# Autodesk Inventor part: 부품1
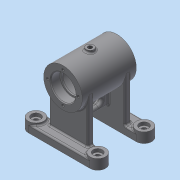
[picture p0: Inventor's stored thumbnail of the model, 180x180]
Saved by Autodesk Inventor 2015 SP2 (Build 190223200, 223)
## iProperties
Created: 2015-11
Part Number: 부품1
Material: 일반
Document SubType Name: Modeling
Designer: AMC
Density: 1 g/cm^3
Appearance: 기본값
Author: AMC
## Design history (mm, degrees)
sketch "스케치1"
  geometry: C1 r 25 at (0, 0); 1 further point
  constraints: 1 centre point, 1 coincident
  dimensions: "d0" = 50 diameter of C1
extrude "돌출1" new body sketch "스케치1" distance "d1" = 70; taper "d2" = 0 deg
sketch "스케치2"
  geometry: C1 r 5 at (0, 35); 1 further point
  constraints: 1 centre point
  dimensions: "d3" = 35 distance of point (0, 0) C1.centre; "d4" = 10 diameter of C1
extrude "돌출2" join sketch "스케치2" distance "d5" = 28; taper "d6" = 0 deg
sketch "스케치3"
  geometry: L1 (25, 70)-(-25, 70) reference; L2 (-25, 0)-(25, 0) reference; L3 (16, 70)-(16, 58); L4 (16, 58)-(14, 58); L5 (14, 58)-(14, 56); L6 (14, 56)-(21, 56); L7 (21, 56)-(21, 14); L8 (21, 14)-(14, 14); L9 (14, 14)-(14, 12); L10 (14, 12)-(16, 12); L11 (16, 12)-(16, 0); L12 (0, 70)-(0, 0)
  constraints: 20 end point, 8 perpendicular, 4 point on line, 1 midpoint, 1 vertical
  dimensions: "d7" = 32 diameter of L3 L12; "d8" = 28 diameter of L5 L12; "d9" = 42 diameter of L7 L12; "d10" = 32 diameter of L11 L12; "d11" = 42 distance of L6.end L7.end; "d12" = 12 distance of L3.start L3.end; "d13" = 12 distance of L10.end L11.end; "d120" = 2 distance of L8.end L9.end
revolve "회전1" sketch "스케치3" stored, may be unused: angle "d14" = 90 deg
sketch "스케치4"
  geometry: 2 further points
hole "구멍1" sketch "스케치4" at (0, 0) diameter "d15" = 5.188; stored, may be unused: countersink angle "d19" = 90 deg, drill point angle "d21" = 118 deg; dims "d16" = 25, "d17" = 4, "d18" = 2, "d20" = 29
node "작업 평면3"
sketch "스케치5"
  geometry: L1 (40, 75)-(-40, 75); L2 (-40, -5)-(40, -5); L3 (40, 55)-(4, 55); L4 (4, 55)-(4, 15); L5 (4, 15)-(40, 15); L6 (-4, 55)-(-40, 55); L7 (-40, 15)-(-4, 15); L8 (-4, 15)-(-4, 55); L9 (40, -5)-(40, 15); L10 (40, 55)-(40, 75); L11 (-40, 75)-(-40, 55); L12 (-40, 15)-(-40, -5); L13 (25, 70)-(-25, 70) reference; L14 (25, 0)-(25, 70) reference; L15 (-25, 0)-(25, 0) reference; L16 (-25, 0)-(-25, 70) reference; L17 (0, 70)-(0, 0); L18 (25, 35)-(-25, 35)
  constraints: 28 end point, 7 parallel, 4 midpoint, 3 horizontal, 3 perpendicular
  dimensions: "d37" = 80 distance of L2.end L1.start; "d38" = 80 distance of L1.start L1.end; "d39" = 20 distance between parallel lines of L1 L3; "d40" = 20 distance between parallel lines of L2 L5; "d43" = 20 distance between parallel lines of L2 L7; "d44" = 20 distance between parallel lines of L1 L6; "d47" = 36 distance of L6.start L6.end; "d48" = 36 distance of L3.start L3.end; "d49" = 36 distance of L7.start L7.end; "d50" = 0 distance between parallel lines of L11 L12; "d51" = 40 distance between parallel lines of L10 L17; "d52" = 40 distance between parallel lines of L1 L18
extrude "돌출3" join sketch "스케치5" distance "d53" = 10; taper "d54" = 0 deg
sketch "스케치6"
  geometry: 2 further points
  dimensions: "d55" = 20 distance of point (0, 20) point (0, 0); "d56" = 0 horizontal distance of point (0, 20) point (0, 0)
hole "구멍2" sketch "스케치6" at (0, 20) diameter "d57" = 3.242; stored, may be unused: countersink angle "d61" = 90 deg, drill point angle "d63" = 118 deg; dims "d58" = 8, "d59" = 4, "d60" = 2, "d62" = 10
sketch "스케치7"
  geometry: 2 further points
  dimensions: "d67" = 0 horizontal distance of point (0, 0) point (0, 20); "d68" = 20 distance of point (0, 20) point (0, 0)
hole "구멍3" sketch "스케치7" at (0, 20) diameter "d69" = 3.242; stored, may be unused: countersink angle "d73" = 90 deg, drill point angle "d75" = 118 deg; dims "d70" = 8, "d71" = 4, "d72" = 2, "d74" = 10
sketch "스케치8"
  geometry: L1 (-40, -5)-(-40, 15) reference; L2 (-40, 55)-(-40, 75) reference; L3 (40, 75)-(40, 55) reference; L4 (40, 15)-(40, -5) reference; 5 further points
  constraints: 4 midpoint, 4 vertical alignment, 8 other
extrude "돌출4" join sketch "스케치8" distance "d79" = 13; taper "d80" = 0 deg
sketch "스케치9"
  geometry: L1 (-80, -10)-(0, -10) reference; L2 (-44, 10)-(-80, 10) reference; L3 (-44, 50)-(-44, 10) reference; L4 (-80, 50)-(-44, 50) reference; L5 (0, 70)-(-80, 70) reference; L6 (-36, 50)-(0, 50) reference; L7 (-36, 10)-(-36, 50) reference; L8 (0, 10)-(-36, 10) reference; A1 r 10 centre (-80, 0) between (-80, 10) and (-80, -10) reference; A2 r 10 centre (-80, 60) between (-80, 70) and (-80, 50) reference; A3 r 10 centre (0, 60) between (0, 50) and (0, 70) reference; A4 r 10 centre (0, 0) between (0, -10) and (0, 10) reference; 2 further points
  constraints: 1 coincident
hole "구멍4" sketch "스케치9" at (0, 0) diameter "d81" = 6; stored, may be unused: countersink angle "d85" = 90 deg, drill point angle "d87" = 118 deg; dims "d82" = 8, "d83" = 12, "d84" = 4, "d86" = 30
sketch "스케치10"
  geometry: L1 (-25, -63)-(25, -63); L2 (-4, -55)-(-40, -55) reference; L3 (-25, -55)-(-0.273, -55); L4 (-0.273, -55)-(25, -55); L5 (-25, -55)-(-25, -63); L6 (25, -63)-(25, -55); L7 (-25, -15)-(25, -15); L8 (25, -15)-(25, -7); L9 (25, -7)-(-25, -7); L10 (-25, -7)-(-25, -15); L11 (-40, -15)-(-4, -15) reference; L12 (-40, -75)-(40, -75) reference; L13 (40, 5)-(-40, 5) reference; L14 (0, -75)-(0, 5); 1 further point
  constraints: 20 end point, 4 horizontal, 3 parallel, 2 midpoint, 2 perpendicular
  dimensions: "d94" = 8 distance between parallel lines of L1 L2; "d99" = 8 distance between parallel lines of L11 L9; "d100" = 50 distance of L1.start L1.end; "d101" = 50 distance of L8.end L9.end; "d102" = 25 distance between parallel lines of L5 L14; "d103" = 25 distance between parallel lines of L10 L14
extrude "돌출5" join sketch "스케치10" stored distance "d104" = 13; taper "d105" = 0 deg
sketch "스케치11"
  geometry: L1 (55, 43)-(-15, 43) reference; L2 (0, 10)-(0, 68) reference; L3 (40, 10)-(40, 68) reference; L4 (0, 23)-(40, 23); L5 (0, 43)-(40, 43); L6 (40, 43)-(40, 23); L7 (40, 23)-(0, 23); L8 (0, 23)-(0, 43); 1 further point
  constraints: 10 end point, 4 point on line, 2 parallel, 2 perpendicular, 1 horizontal
  dimensions: "d106" = 20 distance between parallel lines of L4 L1
extrude "돌출6" join sketch "스케치11" distance "d107" = 8; taper "d108" = 0 deg
sketch "스케치12"
  geometry: L1 (40, 10)-(0, 10) reference; L2 (-36, 0)-(76, 0) reference; L3 (0, 10)-(0, 68) reference; L4 (40, 10)-(40, 68) reference; L5 (0, 10)-(40, 10); L6 (40, 10)-(40, -24.732); L7 (40, -24.732)-(0, -24.732); L8 (0, -24.732)-(0, 10); 1 further point
  constraints: 8 end point, 2 parallel, 1 horizontal, 1 perpendicular
  dimensions: "d109" = 0 distance between parallel lines of L4 L6
extrude "돌출7" cut sketch "스케치12" distance "d110" = 10; taper "d111" = 0 deg
sketch "스케치13"
  geometry: L1 (13.043, 33)-(26.957, 33); L2 (13.043, 28.457)-(26.957, 28.457); L3 (26.957, 37.543)-(13.043, 37.543); L4 (-20, 0)-(-20, 10) reference; L5 (53, 0)-(47, 0) reference; A1 r 4.543 centre (13.043, 33) between (13.043, 37.543) and (13.043, 28.457); A2 r 4.543 centre (26.957, 33) between (26.957, 28.457) and (26.957, 37.543); 2 further points
  constraints: 8 end point, 4 point on circle, 4 tangent, 2 centre point, 1 horizontal, 1 midpoint, 1 parallel
  dimensions: "d113" = 40 distance from line of L4 point (20, 33); "d114" = 33 distance from line of L5 point (20, 33)
extrude "돌출8" cut sketch "스케치13" distance "d115" = 20; taper "d116" = 0 deg
fillet "모깎기1" dims "d117" = 3.5
fillet "모깎기2" dims "d118" = 0.3
fillet "모깎기4" dims "d121" = 0.3
fillet "모깎기5" dims "d122" = 3
fillet "모깎기6" dims "d123" = 2
fillet "모깎기7" dims "d124" = 2
fillet "모깎기8" dims "d125" = 2
fillet "모깎기9" dims "d126" = 2
fillet "모깎기10" dims "d129" = 2
chamfer "모따기1" distance "d130" = 1; stored, may be unused: second distance "d131" = 2, angle "d132" = 45 deg
chamfer "모따기2" distance "d133" = 1; stored, may be unused: second distance "d134" = 2, angle "d135" = 45 deg
node "작업 평면8"
sketch "스케치17"
  geometry: C1 r 6 at (0, 0); 1 further point
  constraints: 1 centre point
  dimensions: "d137" = 12 diameter of C1
extrude "돌출9" join sketch "스케치17" distance "d138" = 3; taper "d139" = 0 deg
sketch "스케치18"
  geometry: L1 (0, -6)-(0, 6) reference; A1 r 6 centre (0, 0) between (0, -6) and (0, 6) reference; 2 further points
  constraints: 1 coincident
hole "구멍5" sketch "스케치18" at (0, 0) diameter "d140" = 5.188; stored, may be unused: countersink angle "d144" = 90 deg, drill point angle "d146" = 118 deg; dims "d141" = 12, "d142" = 12, "d143" = 4, "d145" = 16
node "솔리드1"
pattern_circular "원형 패턴1" dims angle "d65" = 360 deg
pattern_circular "원형 패턴2" dims angle "d77" = 360 deg
pattern_linear "직사각형 패턴1" dims "d90" = 80
pattern_linear "직사각형 패턴2"
node "투영된 루프1"
other parameters: "d24" = -68, "d33" = 32, "d41" = 32
